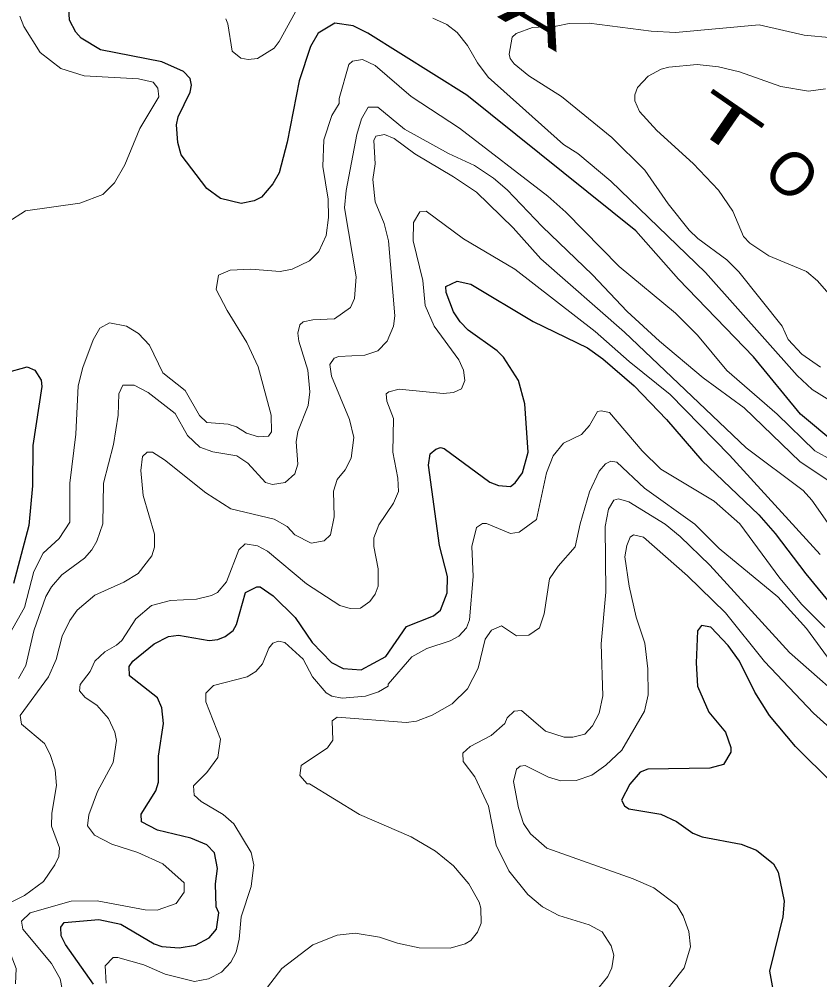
# Model space of a CAD drawing. Extents: x 265 to 291.4, y 7731.5 to 7759.6.
# Drawn here: x 283.863 to 285.338, y 7748.958 to 7750.728 of the extents above; entities that cross this region are included whole.
import ezdxf
from ezdxf.enums import TextEntityAlignment as Align

# ---------------------------------------------------------------- set-up
doc = ezdxf.new("R2010")
doc.units = 0
doc.header["$LTSCALE"] = 0.032
for name, color, linetype, lineweight in [('1', 7, 'Continuous', 25), ('2', 7, 'Continuous', 13), ('61', 7, 'Continuous', 13)]:
    doc.layers.add(name, color=color, linetype=linetype, lineweight=lineweight)

msp = doc.modelspace()

# ---------------------------------------------------------------- linework, layer by layer
at = {"layer": '1'}
for points in [[(284.1612, 7750.4783), (284.1551, 7750.5005), (284.1528, 7750.5331), (284.1559, 7750.5482), (284.1782, 7750.5935), (284.1806, 7750.6063), (284.1782, 7750.619), (284.1655, 7750.6317), (284.1257, 7750.6492), (284.0128, 7750.6715), (283.977, 7750.693), (283.9674, 7750.7041), (283.9555, 7750.7264), (283.9491, 7750.8465)], [(285.3699, 7749.9444), (285.303, 7750.0001), (285.2163, 7750.1059), (285.0779, 7750.2491), (284.9992, 7750.3382), (284.6881, 7750.588), (284.5052, 7750.7025), (284.4781, 7750.716), (284.4447, 7750.7208), (284.4137, 7750.7025), (284.3994, 7750.6779), (284.3787, 7750.6142), (284.3564, 7750.5013), (284.3421, 7750.4448), (284.3301, 7750.4249), (284.3095, 7750.4002), (284.296, 7750.3931), (284.2721, 7750.3883), (284.2339, 7750.3978), (284.2084, 7750.4161), (284.1612, 7750.4783)], [(284.7947, 7750.0192), (284.7828, 7750.0622), (284.7557, 7750.1051), (284.7438, 7750.117), (284.6905, 7750.1552), (284.6754, 7750.1703), (284.6635, 7750.1886), (284.6499, 7750.2244), (284.6491, 7750.2356), (284.6698, 7750.2451), (284.6953, 7750.2395), (284.8098, 7750.1711), (284.9101, 7750.1226), (284.9387, 7750.1019), (284.996, 7750.0526), (285.0556, 7749.9906), (285.1209, 7749.915), (285.2259, 7749.8148), (285.2561, 7749.7806), (285.3126, 7749.7058), (285.3667, 7749.6405)], [(283.8377, 7750.0765), (283.8775, 7750.0876), (283.8919, 7750.0812), (283.903, 7750.063), (283.9046, 7750.051), (283.8879, 7749.9428), (283.8871, 7749.8681), (283.8807, 7749.7949), (283.8521, 7749.6883)], [(284.7303, 7749.8752), (284.7462, 7749.8688), (284.7685, 7749.8672), (284.7772, 7749.8736), (284.7907, 7749.8919), (284.8011, 7749.9301), (284.7947, 7750.0192)], [(284, 7748.9501), (283.9483, 7749.0233), (283.9404, 7749.0392), (283.9396, 7749.0551), (283.9459, 7749.0638), (284.0096, 7749.0694), (284.0502, 7749.0606), (284.1114, 7749.024), (284.1257, 7749.0193), (284.1576, 7749.0169), (284.1878, 7749.0216), (284.2132, 7749.0352), (284.2267, 7749.0511), (284.2307, 7749.0813), (284.2259, 7749.0924), (284.2243, 7749.1346), (284.2283, 7749.1633), (284.2228, 7749.1919), (284.2085, 7749.207), (284.179, 7749.2189), (284.1178, 7749.234), (284.0883, 7749.2492), (284.0875, 7749.2635), (284.1146, 7749.3065), (284.1193, 7749.3224), (284.1193, 7749.3701), (284.1289, 7749.4305), (284.1257, 7749.4592), (284.1177, 7749.4775), (284.066, 7749.518), (284.0652, 7749.5356), (284.0724, 7749.5451), (284.1114, 7749.5769), (284.1377, 7749.5904), (284.1567, 7749.5928), (284.2132, 7749.5833), (284.2291, 7749.5848), (284.2427, 7749.5904), (284.257, 7749.6016), (284.2633, 7749.6127), (284.28, 7749.6716), (284.3007, 7749.6819), (284.3071, 7749.6819), (284.331, 7749.6652), (284.3715, 7749.6254), (284.4025, 7749.5793), (284.4383, 7749.5427), (284.4598, 7749.5315), (284.4932, 7749.5292), (284.5386, 7749.5538), (284.5767, 7749.6087), (284.6261, 7749.6286), (284.6396, 7749.6389), (284.6515, 7749.6708), (284.6523, 7749.701), (284.6372, 7749.7583), (284.6173, 7749.9062), (284.6205, 7749.9269), (284.6308, 7749.9357), (284.6396, 7749.9388), (284.6459, 7749.9372), (284.7303, 7749.8752)], [(285.3627, 7749.32), (285.2935, 7749.3876), (285.2457, 7749.4449), (285.2187, 7749.4878), (285.1901, 7749.5451), (285.1694, 7749.5737), (285.1376, 7749.6079), (285.1201, 7749.6111), (285.1129, 7749.6008), (285.1105, 7749.5419), (285.1129, 7749.499), (285.1336, 7749.4512), (285.1646, 7749.4146), (285.1742, 7749.386), (285.1742, 7749.3772), (285.1607, 7749.355), (285.136, 7749.3478), (285.0214, 7749.3462), (285.0071, 7749.3406), (284.988, 7749.3184), (284.9729, 7749.289), (284.9785, 7749.2786)], [(284.9785, 7749.2786), (284.9864, 7749.273), (285.0453, 7749.2635), (285.074, 7749.2499), (285.1042, 7749.2285), (285.1217, 7749.2213), (285.1933, 7749.2078)], [(285.1933, 7749.2078), (285.2219, 7749.1966), (285.2529, 7749.172), (285.2617, 7749.1561), (285.2728, 7749.1028), (285.2704, 7749.0742), (285.2458, 7748.9739), (285.2561, 7748.9167), (285.2553, 7748.888), (285.2481, 7748.8737), (285.2219, 7748.8482), (285.2131, 7748.8339), (285.2131, 7748.8196), (285.2362, 7748.787), (285.2378, 7748.7767), (285.2275, 7748.7584), (285.2275, 7748.7496), (285.2442, 7748.7361), (285.284, 7748.7353), (285.3317, 7748.7225), (285.3396, 7748.7273)]]:
    msp.add_lwpolyline(points, dxfattribs=at)
at = {"layer": '2'}
for points in [[(283.864, 7750.7336), (283.8712, 7750.7145), (283.9014, 7750.6667), (283.9396, 7750.6373), (283.9825, 7750.6238), (284.0828, 7750.6182), (284.1098, 7750.6118), (284.1186, 7750.6007), (284.1202, 7750.5848), (284.0851, 7750.5267), (284.0573, 7750.4599), (284.0382, 7750.4265), (284.0167, 7750.405), (283.9746, 7750.3891), (283.8744, 7750.3748), (283.8417, 7750.3541)], [(284.3723, 7750.7415), (284.3421, 7750.6866), (284.3325, 7750.6747), (284.3023, 7750.6556), (284.2848, 7750.654), (284.2713, 7750.6564), (284.2554, 7750.6691), (284.2474, 7750.7192), (284.2434, 7750.7288)], [(285.3548, 7750.0264), (285.3245, 7750.0454), (285.2967, 7750.0717), (285.128, 7750.261), (284.953, 7750.4297), (284.8926, 7750.4806), (284.8663, 7750.4973), (284.7271, 7750.6214), (284.7072, 7750.6476), (284.6889, 7750.6795), (284.6698, 7750.7033), (284.6508, 7750.7184), (284.6253, 7750.7296)], [(285.3396, 7750.0868), (285.3054, 7750.1107), (285.28, 7750.1377), (285.2688, 7750.1624), (285.1893, 7750.2626), (285.167, 7750.2849), (285.1137, 7750.3239), (285.0978, 7750.339), (285.0588, 7750.3875), (285.0159, 7750.4496), (284.9554, 7750.51), (284.8623, 7750.5856), (284.8019, 7750.6238), (284.7748, 7750.646), (284.7677, 7750.6556), (284.7661, 7750.6635), (284.7717, 7750.6946), (284.7788, 7750.7017), (284.8086, 7750.7127), (284.8528, 7750.7152), (284.8767, 7750.72), (284.9133, 7750.7208), (285.0278, 7750.7057), (285.0724, 7750.7033), (285.2267, 7750.7176), (285.3094, 7750.6985), (285.3619, 7750.6938)], [(284.4391, 7750.5506), (284.4527, 7750.5729), (284.4527, 7750.5816), (284.4702, 7750.6444), (284.4773, 7750.6508), (284.4956, 7750.654), (284.5187, 7750.6428)], [(284.5187, 7750.6428), (284.5855, 7750.5856), (284.6746, 7750.5275), (284.8369, 7750.4018), (284.8703, 7750.3724), (284.9689, 7750.2722), (285.0724, 7750.1862), (285.1129, 7750.1457), (285.167, 7750.0805), (285.2601, 7750.0001), (285.3293, 7749.9325), (285.3921, 7749.8983)], [(285.3715, 7750.2029), (285.3341, 7750.2459), (285.3142, 7750.2634), (285.2442, 7750.292), (285.2092, 7750.3151), (285.198, 7750.3278), (285.1781, 7750.374), (285.1519, 7750.413), (285.105, 7750.4623), (285.0381, 7750.5227), (285.0063, 7750.5577), (284.9976, 7750.5776), (284.9976, 7750.5888), (285.0023, 7750.6023), (285.0222, 7750.623), (285.0461, 7750.6357), (285.0603, 7750.6397), (285.1121, 7750.6444), (285.1519, 7750.6405), (285.1901, 7750.6309), (285.2665, 7750.6039), (285.3174, 7750.5951), (285.3492, 7750.5999)], [(285.3643, 7749.8712), (285.3023, 7749.9126), (285.1988, 7750.012), (285.1233, 7750.0669), (285.0429, 7750.1345), (284.9833, 7750.1894), (284.9196, 7750.2571), (284.8265, 7750.3461), (284.7621, 7750.4138), (284.7367, 7750.4352), (284.7017, 7750.4583), (284.6539, 7750.4806), (284.5728, 7750.5251), (284.5235, 7750.5657), (284.506, 7750.5657), (284.494, 7750.5442), (284.4853, 7750.5156), (284.4654, 7750.4122), (284.4622, 7750.3804), (284.4837, 7750.2531), (284.4805, 7750.2133), (284.4733, 7750.1966), (284.4439, 7750.1759), (284.4042, 7750.1743), (284.3859, 7750.1703), (284.3803, 7750.1648), (284.3763, 7750.1497), (284.3779, 7750.1345), (284.3946, 7750.0813), (284.3986, 7750.0415), (284.3954, 7750.016), (284.3763, 7749.9683), (284.3731, 7749.9492), (284.3763, 7749.9078), (284.3707, 7749.8903), (284.3532, 7749.8744), (284.3294, 7749.8704), (284.3166, 7749.8744), (284.284, 7749.9102), (284.2641, 7749.9237), (284.2196, 7749.9309), (284.1957, 7749.9396), (284.1727, 7749.9611), (284.1504, 7750.0017), (284.1003, 7750.0399), (284.0748, 7750.0534), (284.0541, 7750.0534), (284.0462, 7750.0375), (284.0454, 7749.9985), (284.0366, 7749.9444), (284.0183, 7749.8728), (284.0167, 7749.7981), (284.0056, 7749.7662), (283.9968, 7749.7503), (283.9833, 7749.7352), (283.9412, 7749.7042), (283.9221, 7749.6819), (283.9117, 7749.6644), (283.8895, 7749.6008), (283.8751, 7749.5371), (283.8616, 7749.5133)], [(283.8457, 7749.596), (283.8728, 7749.6437), (283.8895, 7749.7106), (283.907, 7749.744), (283.9364, 7749.771), (283.9563, 7749.8012), (283.9563, 7749.8728), (283.9674, 7749.9635), (283.9714, 7750.0526), (283.9801, 7750.086), (283.9992, 7750.1369), (284.0112, 7750.1584), (284.0295, 7750.1687), (284.0605, 7750.1624), (284.0828, 7750.1489), (284.1027, 7750.1274), (284.1273, 7750.0765), (284.1687, 7750.0438), (284.1949, 7749.9977), (284.2085, 7749.985), (284.2482, 7749.9818), (284.2633, 7749.977), (284.2816, 7749.9651), (284.3039, 7749.9587), (284.3222, 7749.9595), (284.3278, 7749.9675), (284.327, 7749.9985), (284.3031, 7750.0876), (284.2824, 7750.1322), (284.2458, 7750.191), (284.226, 7750.23), (284.2299, 7750.2563), (284.2514, 7750.2658), (284.2896, 7750.2674), (284.3437, 7750.2634), (284.366, 7750.2674), (284.3978, 7750.2825), (284.4153, 7750.3), (284.4288, 7750.3294), (284.4328, 7750.3629), (284.432, 7750.3963), (284.4224, 7750.4567), (284.424, 7750.506), (284.4391, 7750.5506)], [(283.8728, 7749.1131), (283.9078, 7749.1394), (283.9284, 7749.1696), (283.9356, 7749.1855), (283.9372, 7749.2014), (283.9221, 7749.2412), (283.9229, 7749.2651), (283.9316, 7749.316), (283.9292, 7749.3446), (283.9197, 7749.3733), (283.9093, 7749.3932), (283.8672, 7749.429), (283.8648, 7749.4449), (283.9165, 7749.5165), (283.9308, 7749.5483), (283.942, 7749.5912), (283.9563, 7749.6199), (283.9698, 7749.639), (284.0024, 7749.6668), (284.0557, 7749.6907), (284.082, 7749.7066), (284.1074, 7749.7392), (284.1122, 7749.7551), (284.1122, 7749.779), (284.0915, 7749.8506), (284.0867, 7749.8967), (284.0899, 7749.9222), (284.0987, 7749.9301), (284.1082, 7749.9301), (284.1305, 7749.9158), (284.2069, 7749.8553), (284.253, 7749.8259), (284.3326, 7749.8068), (284.3564, 7749.7933), (284.3707, 7749.7782), (284.401, 7749.7623), (284.4248, 7749.767), (284.4368, 7749.7782), (284.4431, 7749.8108), (284.4423, 7749.8585), (284.4487, 7749.88), (284.4638, 7749.8975), (284.4749, 7749.919), (284.4797, 7749.9572), (284.4718, 7749.9906), (284.4383, 7750.0701), (284.4352, 7750.0916), (284.4431, 7750.1035), (284.4519, 7750.1067), (284.4996, 7750.1091), (284.5235, 7750.117), (284.541, 7750.1345), (284.5529, 7750.1624), (284.5553, 7750.1815), (284.5433, 7750.3199), (284.5354, 7750.3517), (284.5187, 7750.3915), (284.5147, 7750.4329), (284.5187, 7750.4615), (284.5163, 7750.5044), (284.5203, 7750.5124), (284.5362, 7750.5156), (284.5537, 7750.5084), (284.5919, 7750.4798), (284.6635, 7750.4376), (284.7056, 7750.409), (284.7732, 7750.3438), (284.8242, 7750.2865), (284.9785, 7750.1512), (285.2028, 7749.9381), (285.3078, 7749.8593), (285.3237, 7749.8418), (285.3786, 7749.7639)], [(285.3388, 7749.7416), (285.1718, 7749.9245), (285.0628, 7750.0367), (284.9872, 7750.0971), (284.9244, 7750.1528), (284.7764, 7750.2674), (284.6818, 7750.3231), (284.6126, 7750.374), (284.6014, 7750.3732), (284.5895, 7750.3533), (284.5887, 7750.3199), (284.607, 7750.2467), (284.611, 7750.2006), (284.6277, 7750.1624), (284.673, 7750.1003), (284.6818, 7750.0813), (284.6842, 7750.0622), (284.6778, 7750.047), (284.6635, 7750.0399), (284.6444, 7750.0383), (284.5632, 7750.0462), (284.5442, 7750.0415), (284.5394, 7750.0375), (284.5402, 7750.024), (284.5529, 7749.9922), (284.5513, 7749.9301), (284.5608, 7749.8824), (284.5616, 7749.8577), (284.5529, 7749.8362), (284.5258, 7749.7965), (284.5163, 7749.7726), (284.5163, 7749.7567), (284.5243, 7749.7153), (284.5243, 7749.6835), (284.5187, 7749.6684), (284.5091, 7749.6549), (284.4917, 7749.6429), (284.4726, 7749.6421), (284.4535, 7749.6477), (284.3922, 7749.6875), (284.3206, 7749.7479), (284.3023, 7749.7575), (284.2792, 7749.7615), (284.2673, 7749.7503), (284.245, 7749.6915), (284.2283, 7749.6716), (284.2172, 7749.666), (284.1894, 7749.6596), (284.1416, 7749.6572), (284.1066, 7749.6477), (284.078, 7749.623), (284.0517, 7749.5833), (284.0422, 7749.5745), (284.0207, 7749.5626), (284.0024, 7749.5451), (283.9937, 7749.526), (283.9754, 7749.5021), (283.9738, 7749.4902), (283.9841, 7749.4783), (284.0056, 7749.464), (284.0271, 7749.4393), (284.039, 7749.4146), (284.0422, 7749.3987), (284.0358, 7749.3582), (284.0072, 7749.3049), (283.9913, 7749.2619), (283.9889, 7749.242), (284.0016, 7749.2245), (284.0335, 7749.2078), (284.0812, 7749.1927), (284.1273, 7749.172), (284.1671, 7749.137), (284.1671, 7749.1195)], [(284.8162, 7749.806), (284.8345, 7749.8919), (284.8472, 7749.9237), (284.8663, 7749.9468), (284.8989, 7749.9627), (284.914, 7749.9794), (284.9284, 7750.0049), (284.9355, 7750.0065), (284.9506, 7750.0033), (285.0111, 7749.9325), (285.0453, 7749.8991), (285.144, 7749.8402), (285.1909, 7749.798), (285.2648, 7749.6978), (285.3054, 7749.6493), (285.3476, 7749.6071)], [(284.9642, 7749.9118), (284.953, 7749.9134), (284.9435, 7749.9086), (284.9315, 7749.8951), (284.914, 7749.8569), (284.8965, 7749.7981), (284.8878, 7749.7559)], [(285.3595, 7749.5435), (285.3142, 7749.6056), (285.2609, 7749.6636), (285.1527, 7749.7527), (285.1082, 7749.7973), (285.0151, 7749.8641), (284.9642, 7749.9118)], [(284.7884, 7749.4544), (284.8329, 7749.4162), (284.8671, 7749.4051), (284.883, 7749.4051), (284.9053, 7749.4106), (284.9196, 7749.4258), (284.9315, 7749.4496), (284.9387, 7749.4815), (284.9355, 7749.5769), (284.9443, 7749.6724), (284.9427, 7749.7933), (284.949, 7749.8251), (284.9586, 7749.8418), (284.9674, 7749.8442), (284.9864, 7749.8386), (285.0533, 7749.7973), (285.0811, 7749.775), (285.136, 7749.7217), (285.2823, 7749.561), (285.4096, 7749.4496)], [(284.6969, 7749.7567), (284.7056, 7749.7917), (284.7168, 7749.7989), (284.7239, 7749.7989), (284.7685, 7749.7806), (284.7844, 7749.7829), (284.8162, 7749.806)], [(285.3762, 7749.4051), (285.3269, 7749.4496), (285.2362, 7749.5443), (285.1646, 7749.6342), (285.0946, 7749.7026), (285.0135, 7749.7734), (284.9952, 7749.7782), (284.9888, 7749.7734), (284.9825, 7749.7583), (284.9793, 7749.7376), (284.9872, 7749.6835), (285, 7749.6262), (285.0159, 7749.5785), (285.0214, 7749.5308), (285.0222, 7749.483), (285.0151, 7749.4528), (284.9737, 7749.3812), (284.9443, 7749.3534), (284.918, 7749.3351), (284.8894, 7749.3255), (284.8608, 7749.3247), (284.8385, 7749.3311), (284.7955, 7749.3526), (284.786, 7749.3518), (284.7796, 7749.3462), (284.774, 7749.3232), (284.7828, 7749.2746), (284.7923, 7749.246), (284.8051, 7749.2269), (284.8353, 7749.2006), (284.9944, 7749.1442), (285.0326, 7749.1275), (285.0747, 7749.0956), (285.0867, 7749.0758), (285.097, 7749.0471), (285.1002, 7749.0185), (285.0883, 7748.9803), (285.0588, 7748.9429)], [(284.0231, 7748.9517), (284.0215, 7748.9835), (284.0358, 7748.9994), (284.0446, 7748.9994), (284.0923, 7748.9859), (284.1321, 7748.9684), (284.1862, 7748.9548), (284.2116, 7748.9596), (284.2355, 7748.9723), (284.253, 7748.9906), (284.2625, 7749.0089), (284.2681, 7749.0328), (284.2721, 7749.0742), (284.2904, 7749.1299), (284.2952, 7749.1696), (284.2904, 7749.1927), (284.2586, 7749.2452), (284.2387, 7749.2627), (284.1981, 7749.2866), (284.1854, 7749.2985), (284.1838, 7749.3152), (284.2085, 7749.3399), (284.2291, 7749.3677), (284.2339, 7749.4011), (284.2069, 7749.4703), (284.2069, 7749.4862), (284.2212, 7749.5005), (284.2832, 7749.5165), (284.2991, 7749.526), (284.3111, 7749.5403), (284.323, 7749.569), (284.3302, 7749.5785), (284.3405, 7749.5817), (284.3524, 7749.5793), (284.3859, 7749.5491), (284.4033, 7749.5165), (284.4288, 7749.487), (284.4392, 7749.4806), (284.4582, 7749.4767), (284.5012, 7749.4806), (284.5251, 7749.4886), (284.5426, 7749.4989), (284.5426, 7749.5029), (284.5863, 7749.553), (284.6142, 7749.5682), (284.6571, 7749.5825), (284.673, 7749.5912), (284.6873, 7749.6063), (284.6929, 7749.6215), (284.6993, 7749.701), (284.6969, 7749.7567)], [(284.8878, 7749.7559), (284.856, 7749.7201), (284.8401, 7749.697), (284.8305, 7749.6326), (284.8218, 7749.6063), (284.8019, 7749.5928), (284.7796, 7749.592), (284.7518, 7749.6103), (284.7335, 7749.6024), (284.7215, 7749.5857), (284.7088, 7749.5324), (284.6889, 7749.4942), (284.6611, 7749.4663), (284.6237, 7749.4456), (284.5951, 7749.4345), (284.576, 7749.4321), (284.4487, 7749.4417), (284.4399, 7749.4353), (284.4407, 7749.3995), (284.4312, 7749.3852), (284.3827, 7749.3526), (284.3803, 7749.3343), (284.3938, 7749.3192), (284.3978, 7749.3192), (284.4901, 7749.2627), (284.5855, 7749.2213), (284.6301, 7749.1951), (284.6635, 7749.168), (284.6913, 7749.1346), (284.7104, 7749.1012), (284.7136, 7749.0901), (284.7144, 7749.0622), (284.7072, 7749.0455), (284.6953, 7749.0304), (284.6849, 7749.024), (284.6571, 7749.0161), (284.5998, 7749.0169), (284.5601, 7749.0256), (284.5267, 7749.0368), (284.4821, 7749.0439), (284.4487, 7749.04), (284.4042, 7749.0225), (284.3469, 7748.9787), (284.2999, 7748.9183)], [(284.6802, 7749.3757), (284.6937, 7749.3876), (284.7327, 7749.4083), (284.7581, 7749.4305), (284.7621, 7749.4409), (284.7748, 7749.4528), (284.7884, 7749.4544)], [(284.9316, 7748.9445), (284.9475, 7748.9644), (284.9554, 7748.9803), (284.9586, 7749.0034), (284.9538, 7749.0209), (284.9371, 7749.0463), (284.9133, 7749.059), (284.8576, 7749.0765), (284.8274, 7749.0925), (284.8003, 7749.1155), (284.7653, 7749.1585), (284.7422, 7749.2062), (284.7279, 7749.2778), (284.7024, 7749.3319), (284.681, 7749.3605), (284.6802, 7749.3757)], [(284.1671, 7749.1195), (284.152, 7749.0988), (284.117, 7749.0861), (284.0947, 7749.0869), (284.0064, 7749.1036), (283.9587, 7749.1028), (283.8831, 7749.0813)], [(283.8561, 7748.9509), (283.8569, 7748.9787), (283.8449, 7749.0105), (283.8179, 7749.0583), (283.8155, 7749.0774), (283.8234, 7749.0893), (283.8728, 7749.1131)], [(283.8831, 7749.0813), (283.8672, 7749.0662), (283.8696, 7749.0511), (283.9221, 7748.9883), (283.938, 7748.9596), (283.942, 7748.9405)]]:
    msp.add_lwpolyline(points, dxfattribs=at)

# ---------------------------------------------------------------- texts
at = {"layer": '61'}
for s, rotation, width, p in [('A', 329.305, 1.8, (284.7983, 7750.6997)), ('T', 325.39, 1.9, (285.1438, 7750.5012))]:
    msp.add_text(s, height=0.08, rotation=rotation, dxfattribs=dict(at, width=width)).set_placement(p, align=Align.CENTER)
msp.add_text('O', height=0.08, rotation=315.652, dxfattribs=at).set_placement((285.2593, 7750.4142), align=Align.CENTER)

doc.saveas('drawing.dxf')
